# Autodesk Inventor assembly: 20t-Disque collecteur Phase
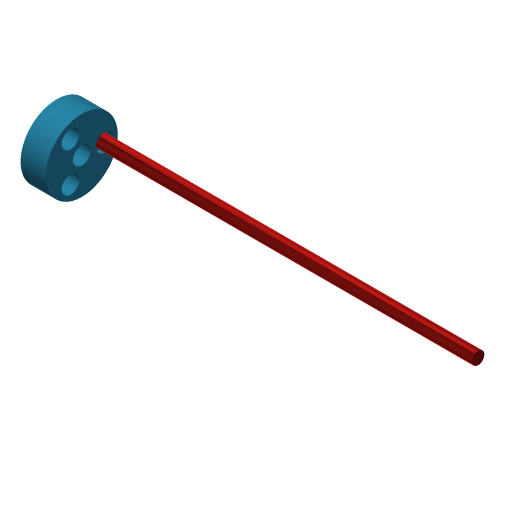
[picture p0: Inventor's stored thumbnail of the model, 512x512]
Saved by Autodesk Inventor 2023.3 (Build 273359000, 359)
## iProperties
Created: 2018-09
Part Number: 20t-Disque collecteur Phase
Material: Générique
Document SubType Name: Assembly
Designer: TJ
Author: TJ
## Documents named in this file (3)
- C:\Travail\BTS TechCom\2-TechnoIndus\21-Meca\214-Systémes Industriels-SI\2141-Pièces Ecrites\21411-Cycle1\214112-TP02Eolienne\2141122-DossierTechniqueEolienne\21411223-Maquette numerique\CEC-Eolienne\Disque collecteur\20t-Disque collecteur Phase.iam
- C:\Travail\BTS TechCom\2-TechnoIndus\21-Meca\214-Systémes Industriels-SI\2141-Pièces Ecrites\21411-Cycle1\214112-TP02Eolienne\2141122-DossierTechniqueEolienne\21411223-Maquette numerique\CEC-Eolienne\Disque collecteur\Disque collecteur n.ipt
- C:\Travail\BTS TechCom\2-TechnoIndus\21-Meca\214-Systémes Industriels-SI\2141-Pièces Ecrites\21411-Cycle1\214112-TP02Eolienne\2141122-DossierTechniqueEolienne\21411223-Maquette numerique\CEC-Eolienne\Disque collecteur\phase.ipt
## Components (2 placed, 2 different names)
1. Disque collecteur n:1 — Logement:1
2. phase:1 — Logement:1
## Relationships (1: Insert 1)
- Logement:1 [Insert]: Disque collecteur n:1 ↔ phase:1
